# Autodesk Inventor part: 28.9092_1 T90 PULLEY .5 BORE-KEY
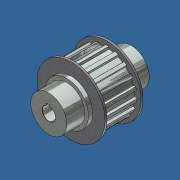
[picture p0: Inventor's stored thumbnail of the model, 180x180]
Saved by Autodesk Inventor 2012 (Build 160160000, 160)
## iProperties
Created: 2006-12
Document SubType Name: Modeling
Designer: Andy Moles
Part Number: 28.9092_1 T90 PULLEY .5 BORE-KEY
Material: Aluminum-6061
Density: 2.71 g/cm^3
Description: T90 PULLEY STAINLESS FLANGE 11mm
Author: Andy Moles
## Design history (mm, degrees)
sketch "Sketch1"
  geometry: L1 (-1.927, 26.982)-(-1.524, 29.17); L2 (1.927, 26.982)-(1.524, 29.17); L3 (11.073, 27.03)-(10.707, 24.842); L4 (15.084, 22.455)-(16.683, 23.977); L5 (19.077, 22.12)-(18.136, 20.071); L6 (21.534, 16.371)-(23.587, 17.23); L7 (25.254, 14.678)-(23.643, 13.144); L8 (25.717, 8.391)-(27.944, 8.508); L9 (28.652, 5.683)-(26.63, 4.755); L10 (27.049, -0.307)-(29.196, -0.889); L11 (28.945, -3.928)-(26.741, -4.085); L12 (25.484, -9.074)-(27.339, -10.286); L13 (26.084, -13.147)-(23.954, -12.569); L14 (21.157, -16.857)-(22.493, -18.635); L15 (20.429, -20.878)-(18.546, -19.693); L16 (14.537, -22.813)-(15.224, -24.929); L17 (12.543, -26.38)-(11.147, -24.648); L18 (6.342, -26.297)-(6.304, -28.522); L19 (3.298, -29.023)-(2.54, -26.931); L20 (-2.54, -26.931)-(-3.298, -29.023); L21 (-6.304, -28.522)-(-6.342, -26.297); L22 (-11.183, -24.631)-(-12.509, -26.396); L23 (-15.224, -24.929)-(-14.537, -22.813); L24 (-18.546, -19.693)-(-20.429, -20.878); L25 (-22.494, -18.635)-(-21.157, -16.856); L26 (-23.935, -12.604)-(-26.101, -13.113); L27 (-27.325, -10.322)-(-25.484, -9.074); L28 (-26.731, -4.15)-(-28.945, -3.928); L29 (-29.196, -0.89)-(-27.049, -0.307); L30 (-26.63, 4.756)-(-28.652, 5.685); L31 (-27.892, 8.674)-(-25.696, 8.455); L32 (-23.643, 13.144)-(-25.254, 14.679); L33 (-23.587, 17.23)-(-21.534, 16.371); L34 (-18.094, 20.109)-(-19.119, 22.083); L35 (-16.714, 23.955)-(-15.052, 22.477); L36 (-10.707, 24.842)-(-11.073, 27.03); L37 (-8.03, 28.085)-(-6.938, 26.146); L38 (6.938, 26.146)-(7.851, 28.135); A1 r 29.21 centre (0, 0) between (-16.714, 23.955) and (-19.119, 22.083); A2 r 27.051 centre (0, 0) between (-10.707, 24.842) and (-15.052, 22.477); A3 r 29.21 centre (0, 0) between (-8.03, 28.085) and (-11.073, 27.03); A4 r 27.051 centre (0, 0) between (-1.927, 26.982) and (-6.938, 26.146); A5 r 29.21 centre (0, 0) between (1.524, 29.17) and (-1.524, 29.17); A6 r 29.21 centre (0, 0) between (11.073, 27.03) and (7.851, 28.135); A7 r 29.21 centre (0, 0) between (19.077, 22.12) and (16.683, 23.977); A8 r 27.051 centre (0, 0) between (15.084, 22.455) and (10.707, 24.842); A9 r 27.051 centre (0, 0) between (21.534, 16.371) and (18.136, 20.071); A10 r 29.21 centre (0, 0) between (25.254, 14.678) and (23.587, 17.23); A11 r 27.051 centre (0, 0) between (25.717, 8.391) and (23.643, 13.144); A12 r 29.21 centre (0, 0) between (28.652, 5.683) and (27.944, 8.508); A13 r 27.051 centre (0, 0) between (27.049, -0.307) and (26.63, 4.755); A14 r 29.21 centre (0, 0) between (28.945, -3.928) and (29.196, -0.889); A15 r 27.051 centre (0, 0) between (25.484, -9.074) and (26.741, -4.085); A16 r 29.21 centre (0, 0) between (26.084, -13.147) and (27.339, -10.286); A17 r 27.051 centre (0, 0) between (21.157, -16.857) and (23.954, -12.569); A18 r 29.21 centre (0, 0) between (20.429, -20.878) and (22.493, -18.635); A19 r 27.051 centre (0, 0) between (14.537, -22.813) and (18.546, -19.693); A20 r 29.21 centre (0, 0) between (12.543, -26.38) and (15.224, -24.929); A21 r 27.051 centre (0, 0) between (6.342, -26.297) and (11.147, -24.648); A22 r 29.21 centre (0, 0) between (3.298, -29.023) and (6.304, -28.522); A23 r 27.051 centre (0, 0) between (-2.54, -26.931) and (2.54, -26.931); A24 r 29.21 centre (0, 0) between (-6.304, -28.522) and (-3.298, -29.023); A25 r 29.21 centre (0, 0) between (-15.224, -24.929) and (-12.509, -26.396); A26 r 29.21 centre (0, 0) between (-22.494, -18.635) and (-20.429, -20.878); A27 r 27.051 centre (0, 0) between (-11.183, -24.631) and (-6.342, -26.297); A28 r 27.051 centre (0, 0) between (-18.546, -19.693) and (-14.537, -22.813); A29 r 29.21 centre (0, 0) between (-27.325, -10.322) and (-26.101, -13.113); A30 r 27.051 centre (0, 0) between (-23.935, -12.604) and (-21.157, -16.856); A31 r 27.051 centre (0, 0) between (-26.731, -4.15) and (-25.484, -9.074); A32 r 29.21 centre (0, 0) between (-29.196, -0.89) and (-28.945, -3.928); A33 r 27.051 centre (0, 0) between (-26.63, 4.756) and (-27.049, -0.307); A34 r 29.21 centre (0, 0) between (-23.587, 17.23) and (-25.254, 14.679); A35 r 29.21 centre (0, 0) between (-27.892, 8.674) and (-28.652, 5.685); A36 r 27.051 centre (0, 0) between (-18.094, 20.109) and (-21.534, 16.371); A37 r 27.051 centre (0, 0) between (-23.643, 13.144) and (-25.696, 8.455); A38 r 27.051 centre (0, 0) between (6.938, 26.146) and (1.927, 26.982); 2 further points
  constraints: 77 point on circle, 76 end point, 38 centre point, 4 parallel, 2 coincident, 2 perpendicular
extrude "Extrusion1" new body sketch "Sketch1" stored distance "d19" = 33.02; taper "d20" = 0 deg
sketch "Sketch4"
  geometry: C1 r 33.02 at (0, 0); A1 r 27.051 centre (0, 0) between (6.938, 26.146) and (1.927, 26.982) reference
  constraints: 1 centre point, 1 coincident
  dimensions: "d24" = 66.04 diameter of C1
extrude "Extrusion3" join sketch "Sketch4" distance "d25" = 1.905; taper "d26" = 0 deg
sketch "Sketch5"
  geometry: C1 r 33.02 at (0, 0) reference; C2 r 21 at (0, 0)
  constraints: 1 centre point, 1 coincident
  dimensions: "d34" = 42 diameter of C2
extrude "Extrusion4" join sketch "Sketch5" distance "d29" = 4.085; taper "d30" = 0 deg
sketch "Sketch7"
  geometry: C1 r 21 at (0, 0) reference; C2 r 17.5 at (0, 0); 1 further point
  constraints: 1 centre point, 1 coincident
  dimensions: "d35" = 35 diameter of C2
extrude "Extrusion6" join sketch "Sketch7" distance "d36" = 17.5; taper "d37" = 0 deg
mirror "Mirror1"
sketch "Sketch8"
  geometry: L1 (0, 0)-(-4.428, 26.534); L2 (-8.03, 28.085)-(-6.938, 26.146) reference; L3 (-1.927, 26.982)-(-1.524, 29.17) reference; L4 (-2.578, 5.803)-(-2.862, 7.505); L5 (-2.862, 7.505)-(0.27, 8.028); L6 (0.27, 8.028)-(0.554, 6.326); C1 r 17.5 at (0, 0) reference; A1 r 6.35 centre (0, 0) between (-2.578, 5.803) and (0.554, 6.326); 1 further point
  constraints: 8 end point, 2 parallel, 2 point on circle, 1 centre point, 1 coincident, 1 midpoint, 1 perpendicular, 1 point on line
  dimensions: "d55" = 12.7 diameter of A1; "d56" = 19.92 deg angle of L1 L2; "d57" = 19.9212 deg angle of L3 L1 (derived); "d58" = 3.175 distance of L4.end L5.end; "d59" = 14.224 dimension on A1 L5
extrude "Extrusion7" cut sketch "Sketch8" stored distance "d39" = 17.5; taper "d40" = 0 deg
chamfer "Chamfer2" distance "d60" = 0.254; stored, may be unused: second distance "d61" = 2, angle "d62" = 45 deg
body "Solid1"
other parameters: "d1" = 2.159, "BORE_DIA" = 11 [user parameter], "SQUARE_KEY_WIDTH" = 4 [user parameter], "t2_KEYWAY_DEPTH" = 1.8 [user parameter]
